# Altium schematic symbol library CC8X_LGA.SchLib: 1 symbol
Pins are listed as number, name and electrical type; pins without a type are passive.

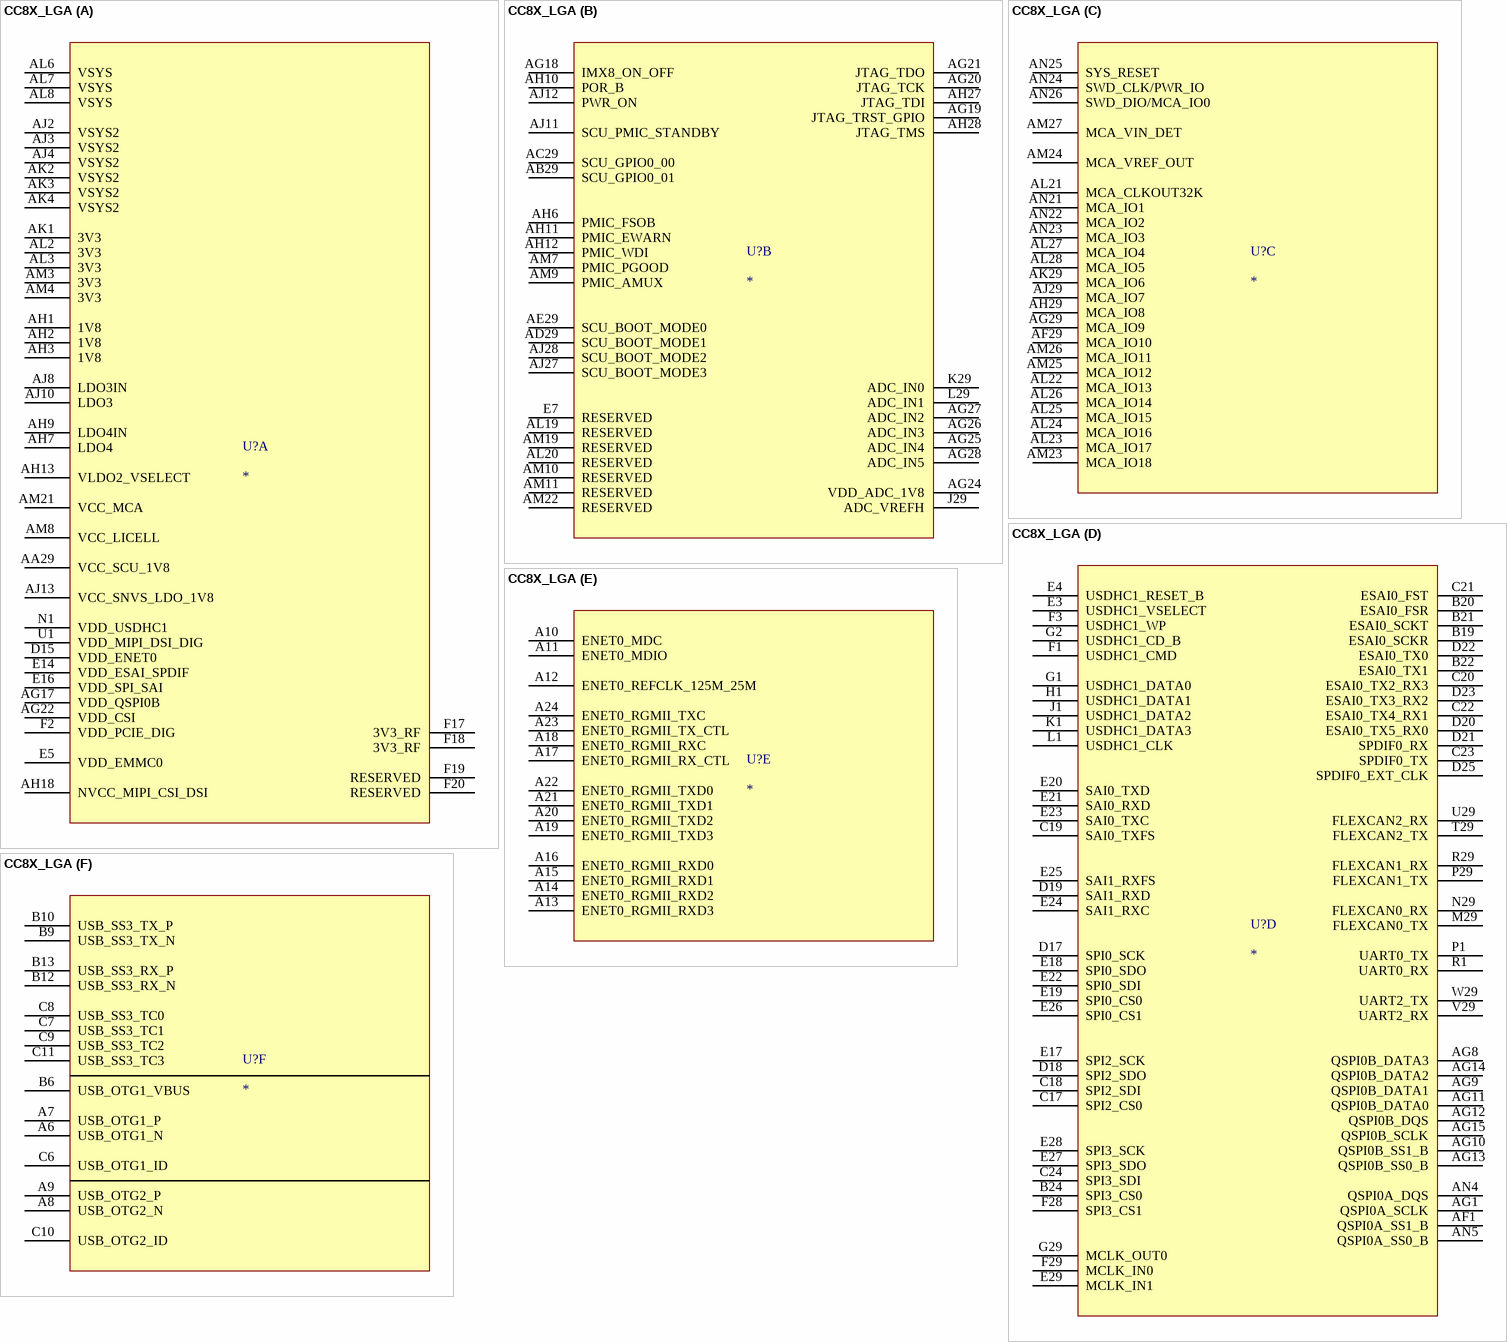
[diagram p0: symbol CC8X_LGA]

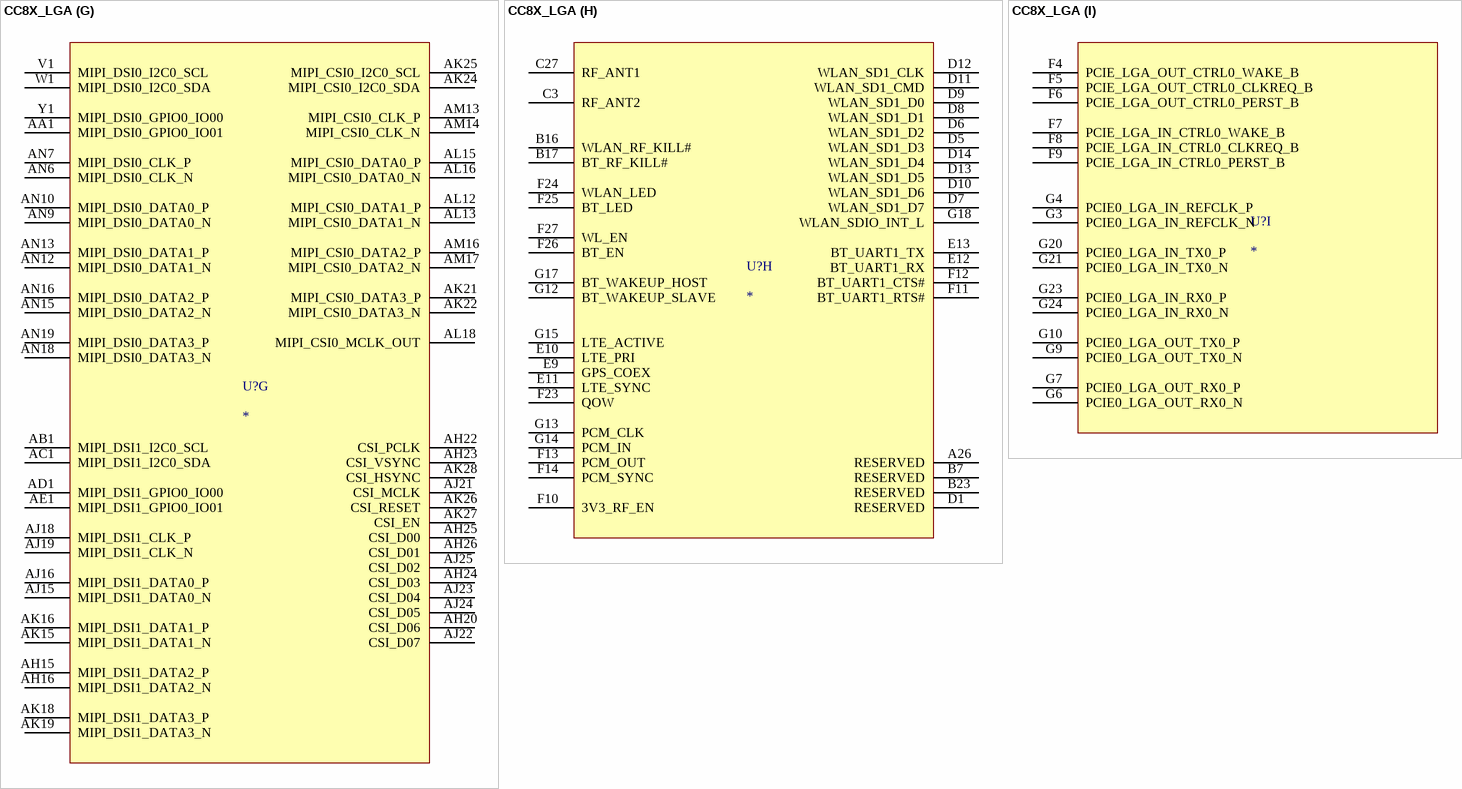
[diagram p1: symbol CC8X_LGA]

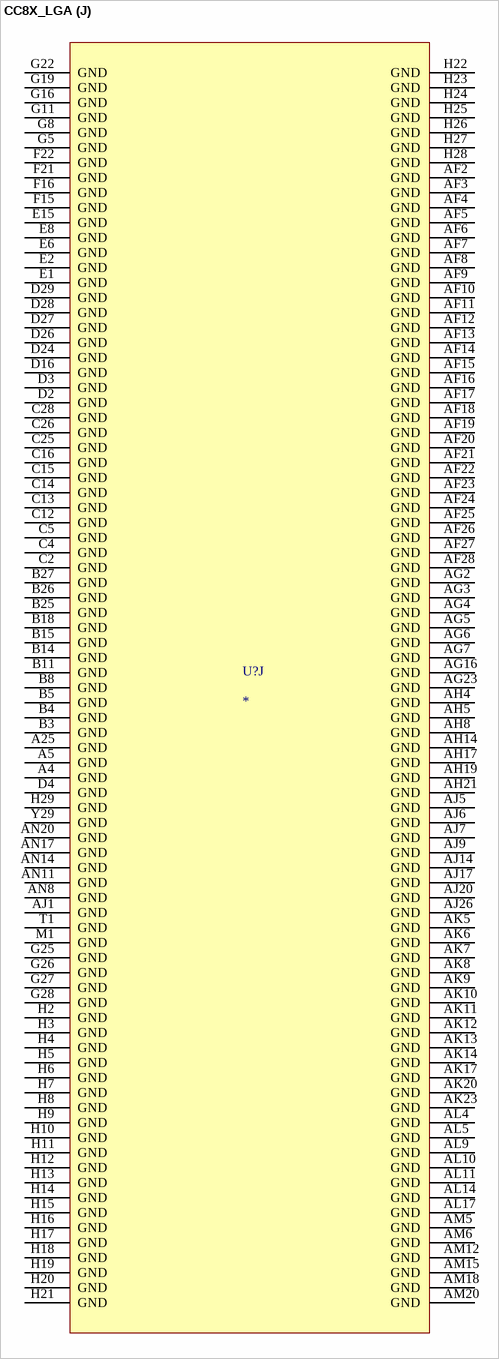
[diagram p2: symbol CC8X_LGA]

## CC8X_LGA
designator U?
CC8X_LGA
part A pins: AA29 VCC_SCU_1V8, AG17 VDD_QSPI0B, AG22 VDD_CSI, AH1 1V8, AH2 1V8, AH3 1V8, AH7 LDO4, AH9 LDO4IN, AH13 VLDO2_VSELECT, AH18 NVCC_MIPI_CSI_DSI, AJ2 VSYS2, AJ3 VSYS2, AJ4 VSYS2, AJ8 LDO3IN, AJ10 LDO3, AJ13 VCC_SNVS_LDO_1V8, AK1 3V3, AK2 VSYS2, AK3 VSYS2, AK4 VSYS2, AL2 3V3, AL3 3V3, AL6 VSYS, AL7 VSYS, AL8 VSYS, AM3 3V3, AM4 3V3, AM8 VCC_LICELL, AM21 VCC_MCA, D15 VDD_ENET0, E5 VDD_EMMC0, E14 VDD_ESAI_SPDIF, E16 VDD_SPI_SAI, F2 VDD_PCIE_DIG, F17 3V3_RF, F18 3V3_RF, F19 RESERVED, F20 RESERVED, N1 VDD_USDHC1, U1 VDD_MIPI_DSI_DIG
part B pins: AB29 SCU_GPIO0_01, AC29 SCU_GPIO0_00, AD29 SCU_BOOT_MODE1, AE29 SCU_BOOT_MODE0, AG18 IMX8_ON_OFF, AG19 JTAG_TRST_GPIO, AG20 JTAG_TCK, AG21 JTAG_TDO, AG24 VDD_ADC_1V8, AG25 ADC_IN4, AG26 ADC_IN3, AG27 ADC_IN2, AG28 ADC_IN5, AH6 PMIC_FSOB, AH10 POR_B, AH11 PMIC_EWARN, AH12 PMIC_WDI, AH27 JTAG_TDI, AH28 JTAG_TMS, AJ11 SCU_PMIC_STANDBY, AJ12 PWR_ON, AJ27 SCU_BOOT_MODE3, AJ28 SCU_BOOT_MODE2, AL19 RESERVED, AL20 RESERVED, AM7 PMIC_PGOOD, AM9 PMIC_AMUX, AM10 RESERVED, AM11 RESERVED, AM19 RESERVED, AM22 RESERVED, E7 RESERVED, J29 ADC_VREFH, K29 ADC_IN0, L29 ADC_IN1
part C pins: AF29 MCA_IO10, AG29 MCA_IO9, AH29 MCA_IO8, AJ29 MCA_IO7, AK29 MCA_IO6, AL21 MCA_CLKOUT32K, AL22 MCA_IO13, AL23 MCA_IO17, AL24 MCA_IO16, AL25 MCA_IO15, AL26 MCA_IO14, AL27 MCA_IO4, AL28 MCA_IO5, AM23 MCA_IO18, AM24 MCA_VREF_OUT, AM25 MCA_IO12, AM26 MCA_IO11, AM27 MCA_VIN_DET, AN21 MCA_IO1, AN22 MCA_IO2, AN23 MCA_IO3, AN24 SWD_CLK/PWR_IO, AN25 SYS_RESET, AN26 SWD_DIO/MCA_IO0
part D pins: AF1 QSPI0A_SS1_B, AG1 QSPI0A_SCLK, AG8 QSPI0B_DATA3, AG9 QSPI0B_DATA1, AG10 QSPI0B_SS1_B, AG11 QSPI0B_DATA0, AG12 QSPI0B_DQS, AG13 QSPI0B_SS0_B, AG14 QSPI0B_DATA2, AG15 QSPI0B_SCLK, AN4 QSPI0A_DQS, AN5 QSPI0A_SS0_B, B19 ESAI0_SCKR, B20 ESAI0_FSR, B21 ESAI0_SCKT, B22 ESAI0_TX1, B24 SPI3_CS0, C17 SPI2_CS0, C18 SPI2_SDI, C19 SAI0_TXFS, C20 ESAI0_TX2_RX3, C21 ESAI0_FST, C22 ESAI0_TX4_RX1, C23 SPDIF0_TX, C24 SPI3_SDI, D17 SPI0_SCK, D18 SPI2_SDO, D19 SAI1_RXD, D20 ESAI0_TX5_RX0, D21 SPDIF0_RX, D22 ESAI0_TX0, D23 ESAI0_TX3_RX2, D25 SPDIF0_EXT_CLK, E3 USDHC1_VSELECT, E4 USDHC1_RESET_B, E17 SPI2_SCK, E18 SPI0_SDO, E19 SPI0_CS0, E20 SAI0_TXD, E21 SAI0_RXD, E22 SPI0_SDI, E23 SAI0_TXC, E24 SAI1_RXC, E25 SAI1_RXFS, E26 SPI0_CS1, E27 SPI3_SDO, E28 SPI3_SCK, E29 MCLK_IN1, F1 USDHC1_CMD, F3 USDHC1_WP, F28 SPI3_CS1, F29 MCLK_IN0, G1 USDHC1_DATA0, G2 USDHC1_CD_B, G29 MCLK_OUT0, H1 USDHC1_DATA1, J1 USDHC1_DATA2, K1 USDHC1_DATA3, L1 USDHC1_CLK, M29 FLEXCAN0_TX, N29 FLEXCAN0_RX, P1 UART0_TX, P29 FLEXCAN1_TX, R1 UART0_RX, R29 FLEXCAN1_RX, T29 FLEXCAN2_TX, U29 FLEXCAN2_RX, V29 UART2_RX, W29 UART2_TX
part E pins: A10 ENET0_MDC, A11 ENET0_MDIO, A12 ENET0_REFCLK_125M_25M, A13 ENET0_RGMII_RXD3, A14 ENET0_RGMII_RXD2, A15 ENET0_RGMII_RXD1, A16 ENET0_RGMII_RXD0, A17 ENET0_RGMII_RX_CTL, A18 ENET0_RGMII_RXC, A19 ENET0_RGMII_TXD3, A20 ENET0_RGMII_TXD2, A21 ENET0_RGMII_TXD1, A22 ENET0_RGMII_TXD0, A23 ENET0_RGMII_TX_CTL, A24 ENET0_RGMII_TXC
part F pins: A6 USB_OTG1_N, A7 USB_OTG1_P, A8 USB_OTG2_N, A9 USB_OTG2_P, B6 USB_OTG1_VBUS, B9 USB_SS3_TX_N, B10 USB_SS3_TX_P, B12 USB_SS3_RX_N, B13 USB_SS3_RX_P, C6 USB_OTG1_ID, C7 USB_SS3_TC1, C8 USB_SS3_TC0, C9 USB_SS3_TC2, C10 USB_OTG2_ID, C11 USB_SS3_TC3
part G pins: AA1 MIPI_DSI0_GPIO0_IO01, AB1 MIPI_DSI1_I2C0_SCL, AC1 MIPI_DSI1_I2C0_SDA, AD1 MIPI_DSI1_GPIO0_IO00, AE1 MIPI_DSI1_GPIO0_IO01, AH15 MIPI_DSI1_DATA2_P, AH16 MIPI_DSI1_DATA2_N, AH20 CSI_D06, AH22 CSI_PCLK, AH23 CSI_VSYNC, AH24 CSI_D03, AH25 CSI_D00, AH26 CSI_D01, AJ15 MIPI_DSI1_DATA0_N, AJ16 MIPI_DSI1_DATA0_P, AJ18 MIPI_DSI1_CLK_P, AJ19 MIPI_DSI1_CLK_N, AJ21 CSI_MCLK, AJ22 CSI_D07, AJ23 CSI_D04, AJ24 CSI_D05, AJ25 CSI_D02, AK15 MIPI_DSI1_DATA1_N, AK16 MIPI_DSI1_DATA1_P, AK18 MIPI_DSI1_DATA3_P, AK19 MIPI_DSI1_DATA3_N, AK21 MIPI_CSI0_DATA3_P, AK22 MIPI_CSI0_DATA3_N, AK24 MIPI_CSI0_I2C0_SDA, AK25 MIPI_CSI0_I2C0_SCL, AK26 CSI_RESET, AK27 CSI_EN, AK28 CSI_HSYNC, AL12 MIPI_CSI0_DATA1_P, AL13 MIPI_CSI0_DATA1_N, AL15 MIPI_CSI0_DATA0_P, AL16 MIPI_CSI0_DATA0_N, AL18 MIPI_CSI0_MCLK_OUT, AM13 MIPI_CSI0_CLK_P, AM14 MIPI_CSI0_CLK_N, AM16 MIPI_CSI0_DATA2_P, AM17 MIPI_CSI0_DATA2_N, AN6 MIPI_DSI0_CLK_N, AN7 MIPI_DSI0_CLK_P, AN9 MIPI_DSI0_DATA0_N, AN10 MIPI_DSI0_DATA0_P, AN12 MIPI_DSI0_DATA1_N, AN13 MIPI_DSI0_DATA1_P, AN15 MIPI_DSI0_DATA2_N, AN16 MIPI_DSI0_DATA2_P, AN18 MIPI_DSI0_DATA3_N, AN19 MIPI_DSI0_DATA3_P, V1 MIPI_DSI0_I2C0_SCL, W1 MIPI_DSI0_I2C0_SDA, Y1 MIPI_DSI0_GPIO0_IO00
part H pins: A26 RESERVED, B7 RESERVED, B16 WLAN_RF_KILL#, B17 BT_RF_KILL#, B23 RESERVED, C3 RF_ANT2, C27 RF_ANT1, D1 RESERVED, D5 WLAN_SD1_D3, D6 WLAN_SD1_D2, D7 WLAN_SD1_D7, D8 WLAN_SD1_D1, D9 WLAN_SD1_D0, D10 WLAN_SD1_D6, D11 WLAN_SD1_CMD, D12 WLAN_SD1_CLK, D13 WLAN_SD1_D5, D14 WLAN_SD1_D4, E9 GPS_COEX, E10 LTE_PRI, E11 LTE_SYNC, E12 BT_UART1_RX, E13 BT_UART1_TX, F10 3V3_RF_EN, F11 BT_UART1_RTS#, F12 BT_UART1_CTS#, F13 PCM_OUT, F14 PCM_SYNC, F23 QOW, F24 WLAN_LED, F25 BT_LED, F26 BT_EN, F27 WL_EN, G12 BT_WAKEUP_SLAVE, G13 PCM_CLK, G14 PCM_IN, G15 LTE_ACTIVE, G17 BT_WAKEUP_HOST, G18 WLAN_SDIO_INT_L
part I pins: F4 PCIE_LGA_OUT_CTRL0_WAKE_B, F5 PCIE_LGA_OUT_CTRL0_CLKREQ_B, F6 PCIE_LGA_OUT_CTRL0_PERST_B, F7 PCIE_LGA_IN_CTRL0_WAKE_B, F8 PCIE_LGA_IN_CTRL0_CLKREQ_B, F9 PCIE_LGA_IN_CTRL0_PERST_B, G3 PCIE0_LGA_IN_REFCLK_N, G4 PCIE0_LGA_IN_REFCLK_P, G6 PCIE0_LGA_OUT_RX0_N, G7 PCIE0_LGA_OUT_RX0_P, G9 PCIE0_LGA_OUT_TX0_N, G10 PCIE0_LGA_OUT_TX0_P, G20 PCIE0_LGA_IN_TX0_P, G21 PCIE0_LGA_IN_TX0_N, G23 PCIE0_LGA_IN_RX0_P, G24 PCIE0_LGA_IN_RX0_N
part J pins:  A25 GND, A4 GND, A5 GND, AF2 GND, AF3 GND, AF4 GND, AF5 GND, AF6 GND, AF7 GND, AF8 GND, AF9 GND, AF10 GND, AF11 GND, AF12 GND, AF13 GND, AF14 GND, AF15 GND, AF16 GND, AF17 GND, AF18 GND, AF19 GND, AF20 GND, AF21 GND, AF22 GND, AF23 GND, AF24 GND, AF25 GND, AF26 GND, AF27 GND, AF28 GND, AG2 GND, AG3 GND, AG4 GND, AG5 GND, AG6 GND, AG7 GND, AG16 GND, AG23 GND, AH4 GND, AH5 GND, AH8 GND, AH14 GND, AH17 GND, AH19 GND, AH21 GND, AJ1 GND, AJ5 GND, AJ6 GND, AJ7 GND, AJ9 GND, AJ14 GND, AJ17 GND, AJ20 GND, AJ26 GND, AK5 GND, AK6 GND, AK7 GND, AK8 GND, AK9 GND, AK10 GND, AK11 GND, AK12 GND, AK13 GND, AK14 GND, AK17 GND, AK20 GND, AK23 GND, AL4 GND, AL5 GND, AL9 GND, AL10 GND, AL11 GND, AL14 GND, AL17 GND, AM5 GND, AM6 GND, AM12 GND, AM15 GND, AM18 GND, AM20 GND, AN8 GND, AN11 GND, AN14 GND, AN17 GND, AN20 GND, B3 GND, B4 GND, B5 GND, B8 GND, B11 GND, B14 GND, B15 GND, B18 GND, B25 GND, B26 GND, B27 GND, C2 GND, C4 GND, C5 GND, C12 GND, C13 GND, C14 GND, C15 GND, C16 GND, C25 GND, C26 GND, C28 GND, D2 GND, D3 GND, D4 GND, D16 GND, D24 GND, D26 GND, D27 GND, D28 GND, D29 GND, E1 GND, E2 GND, E6 GND, E8 GND, E15 GND, F15 GND, F16 GND, F21 GND, F22 GND, G5 GND, G8 GND, G11 GND, G16 GND, G19 GND, G22 GND, G25 GND, G26 GND, G27 GND, G28 GND, H2 GND, H3 GND, H4 GND, H5 GND, H6 GND, H7 GND, H8 GND, H9 GND, H10 GND, H11 GND, H12 GND, H13 GND, H14 GND, H15 GND, H16 GND, H17 GND, H18 GND, H19 GND, H20 GND, H21 GND, H22 GND, H23 GND, H24 GND, H25 GND, H26 GND, H27 GND, H28 GND, H29 GND, M1 GND, T1 GND, Y29 GND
